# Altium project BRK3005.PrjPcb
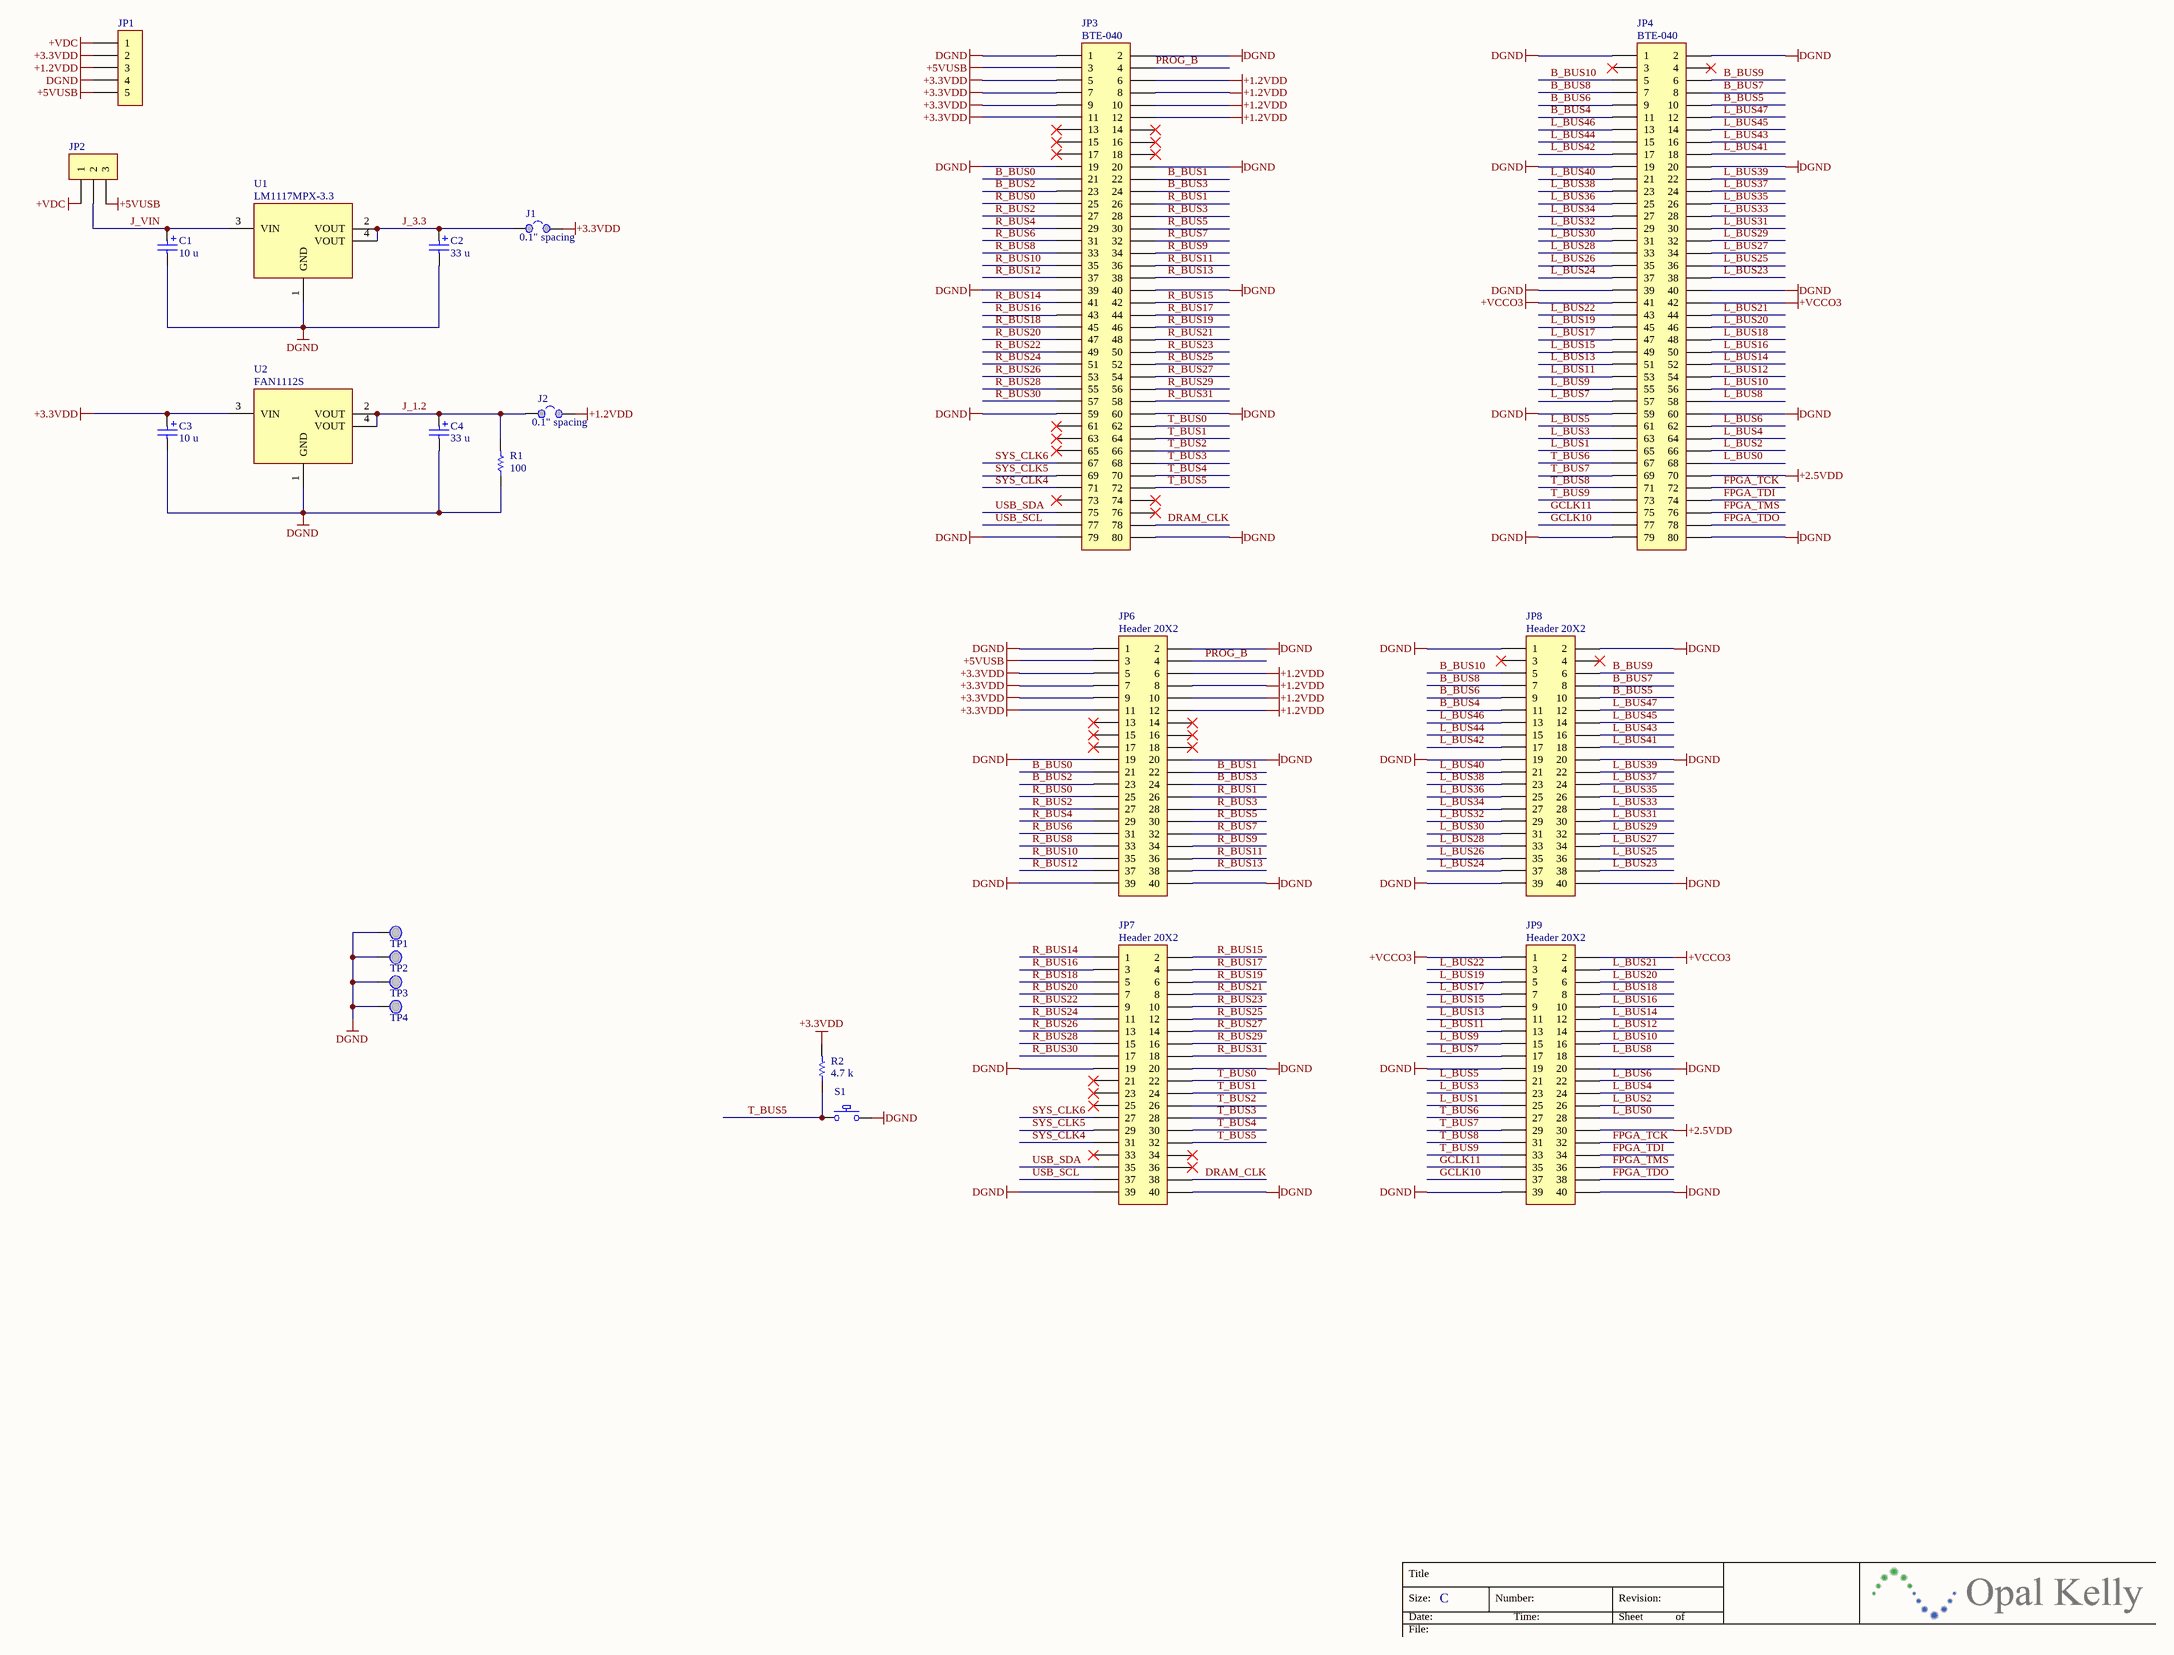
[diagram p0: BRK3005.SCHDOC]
1 sheet, 23 parts. Net scope: global (net labels, ports and power ports of the same name join across sheets).
Board file: BRK3005.PcbDoc

## Sheet BRK3005.SCHDOC: BRK3005
size C; Author: Garrick Kremesec; Organization: Opal Kelly; Address1: 13500 SW 72nd Ave, STE 120; Address2: Portland, OR  97223; Address3: http://www.opalkelly.com; DocumentNumber: xxx; Revision: 1; SheetNumber: 1; SheetTotal: 1; PageSetup: Record=PageOptions|CenterHorizontal=True|CenterVertical=True|PrintScale=0.54|XCorrection=1.00|YCorrection=1.00|PrintKind=0|BorderSize=5000000|LeftOffset=0|BottomOffset=0|Orientation=2|PaperLength=1000|PaperWidth=1000|Scale=100|PaperSource=7|PrintQuality=-4|MediaType=1|DitherType=10|PaperKind=Letter|PrintScaleMode=1

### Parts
C1  value 10 u  [TC3216-1206]  (hidden comment: SM-A, 10v, 10%)
C2  value 33 u  [TC3528-1411]  (hidden comment: SM-B, 10v, low-ESR)
C3  value 10 u  [TC3216-1206]  (hidden comment: SM-A, 10v, 10%)
C4  value 33 u  [TC3528-1411]  (hidden comment: SM-B, 10v, low-ESR)
J1  0.1" spacing  [HDR1X2]
J2  0.1" spacing  [HDR1X2]
JP1  Header, 6-Pin, Single Row  [HDR1X5]  (value not drawn)
JP2  *  [HDR1X3]  (value not drawn)
JP3  BTE-040  [BTE-040]
JP4  BTE-040  [BTE-040]
JP6  Header 20X2  [HDR2X20]
JP7  Header 20X2  [HDR2X20]
JP8  Header 20X2  [HDR2X20]
JP9  Header 20X2  [HDR2X20]
R1  value 100  [CR1608-0603]  (hidden comment: SM-0603, 5%, 1/10W)
R2  value 4.7 k  [CR1608-0603]  (hidden comment: SM-0603, 5%, 1/10W)
S1  SMD, tactile  [SW_BFS]  (value not drawn)
TP1  TESTPOINT  [TP_MED]  (value not drawn)
TP2  TESTPOINT  [TP_MED]  (value not drawn)
TP3  TESTPOINT  [TP_MED]  (value not drawn)
TP4  TESTPOINT  [TP_MED]  (value not drawn)
U1  ManufacturerPartNumber: LM1117MPX-3.3  [DSO-G3]  (hidden comment: 3.3v 800mA)
U2  ManufacturerPartNumber: FAN1112S  [DSO-G3]  (hidden comment: 1.2v 1A)

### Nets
+1.2VDD: J2.2 JP1.3 JP3.6 JP3.8 JP3.10 JP3.12 JP6.6 JP6.8 JP6.10 JP6.12
+2.5VDD: JP4.70 JP9.30
+3.3VDD: C3.1 J1.2 JP1.2 JP3.5 JP3.7 JP3.9 JP3.11 JP6.5 JP6.7 JP6.9 JP6.11 R2.2 U2.3(VIN)
+5VUSB: JP1.5 JP2.3 JP3.3 JP6.3
+VCCO3: JP4.41 JP4.42 JP9.1 JP9.2
+VDC: JP1.1 JP2.1
DGND: C1.2 C2.2 C3.2 C4.2 JP1.4 JP3.1 JP3.2 JP3.19 JP3.20 JP3.39 JP3.40 JP3.59 JP3.60 JP3.79 JP3.80 JP4.1 JP4.2 JP4.19 JP4.20 JP4.39 JP4.40 JP4.59 JP4.60 JP4.79 JP4.80 JP6.1 JP6.2 JP6.19 JP6.20 JP6.39 JP6.40 JP7.19 JP7.20 JP7.39 JP7.40 JP8.1 JP8.2 JP8.19 JP8.20 JP8.39 JP8.40 JP9.19 JP9.20 JP9.39 JP9.40 R1.1 S1.2 TP1.1(PIN) TP2.1(PIN) TP3.1(PIN) TP4.1(PIN) U1.1(GND) U2.1(GND)
B_BUS0: JP3.21 JP6.21
B_BUS1: JP3.22 JP6.22
B_BUS2: JP3.23 JP6.23
B_BUS3: JP3.24 JP6.24
B_BUS4: JP4.11 JP8.11
B_BUS5: JP4.10 JP8.10
B_BUS6: JP4.9 JP8.9
B_BUS7: JP4.8 JP8.8
B_BUS8: JP4.7 JP8.7
B_BUS9: JP4.6 JP8.6
B_BUS10: JP4.5 JP8.5
DRAM_CLK: JP3.78 JP7.38
FPGA_TCK: JP4.72 JP9.32
FPGA_TDI: JP4.74 JP9.34
FPGA_TDO: JP4.78 JP9.38
FPGA_TMS: JP4.76 JP9.36
GCLK10: JP4.77 JP9.37
GCLK11: JP4.75 JP9.35
J_1.2: C4.1 J2.1 R1.2 U2.2(VOUT) U2.4(VOUT)
J_3.3: C2.1 J1.1 U1.2(VOUT) U1.4(VOUT)
J_VIN: C1.1 JP2.2 U1.3(VIN)
L_BUS0: JP4.68 JP9.28
L_BUS1: JP4.65 JP9.25
L_BUS2: JP4.66 JP9.26
L_BUS3: JP4.63 JP9.23
L_BUS4: JP4.64 JP9.24
L_BUS5: JP4.61 JP9.21
L_BUS6: JP4.62 JP9.22
L_BUS7: JP4.57 JP9.17
L_BUS8: JP4.58 JP9.18
L_BUS9: JP4.55 JP9.15
L_BUS10: JP4.56 JP9.16
L_BUS11: JP4.53 JP9.13
L_BUS12: JP4.54 JP9.14
L_BUS13: JP4.51 JP9.11
L_BUS14: JP4.52 JP9.12
L_BUS15: JP4.49 JP9.9
L_BUS16: JP4.50 JP9.10
L_BUS17: JP4.47 JP9.7
L_BUS18: JP4.48 JP9.8
L_BUS19: JP4.45 JP9.5
L_BUS20: JP4.46 JP9.6
L_BUS21: JP4.44 JP9.4
L_BUS22: JP4.43 JP9.3
L_BUS23: JP4.38 JP8.38
L_BUS24: JP4.37 JP8.37
L_BUS25: JP4.36 JP8.36
L_BUS26: JP4.35 JP8.35
L_BUS27: JP4.34 JP8.34
L_BUS28: JP4.33 JP8.33
L_BUS29: JP4.32 JP8.32
L_BUS30: JP4.31 JP8.31
L_BUS31: JP4.30 JP8.30
L_BUS32: JP4.29 JP8.29
L_BUS33: JP4.28 JP8.28
L_BUS34: JP4.27 JP8.27
L_BUS35: JP4.26 JP8.26
L_BUS36: JP4.25 JP8.25
L_BUS37: JP4.24 JP8.24
L_BUS38: JP4.23 JP8.23
L_BUS39: JP4.22 JP8.22
L_BUS40: JP4.21 JP8.21
L_BUS41: JP4.18 JP8.18
L_BUS42: JP4.17 JP8.17
L_BUS43: JP4.16 JP8.16
L_BUS44: JP4.15 JP8.15
L_BUS45: JP4.14 JP8.14
L_BUS46: JP4.13 JP8.13
L_BUS47: JP4.12 JP8.12
PROG_B: JP3.4 JP6.4
R_BUS0: JP3.25 JP6.25
R_BUS1: JP3.26 JP6.26
R_BUS2: JP3.27 JP6.27
R_BUS3: JP3.28 JP6.28
R_BUS4: JP3.29 JP6.29
R_BUS5: JP3.30 JP6.30
R_BUS6: JP3.31 JP6.31
R_BUS7: JP3.32 JP6.32
R_BUS8: JP3.33 JP6.33
R_BUS9: JP3.34 JP6.34
R_BUS10: JP3.35 JP6.35
R_BUS11: JP3.36 JP6.36
R_BUS12: JP3.37 JP6.37
R_BUS13: JP3.38 JP6.38
R_BUS14: JP3.41 JP7.1
R_BUS15: JP3.42 JP7.2
R_BUS16: JP3.43 JP7.3
R_BUS17: JP3.44 JP7.4
R_BUS18: JP3.45 JP7.5
R_BUS19: JP3.46 JP7.6
R_BUS20: JP3.47 JP7.7
R_BUS21: JP3.48 JP7.8
R_BUS22: JP3.49 JP7.9
R_BUS23: JP3.50 JP7.10
R_BUS24: JP3.51 JP7.11
R_BUS25: JP3.52 JP7.12
R_BUS26: JP3.53 JP7.13
R_BUS27: JP3.54 JP7.14
R_BUS28: JP3.55 JP7.15
R_BUS29: JP3.56 JP7.16
R_BUS30: JP3.57 JP7.17
R_BUS31: JP3.58 JP7.18
SYS_CLK4: JP3.71 JP7.31
SYS_CLK5: JP3.69 JP7.29
SYS_CLK6: JP3.67 JP7.27
T_BUS0: JP3.62 JP7.22
T_BUS1: JP3.64 JP7.24
T_BUS2: JP3.66 JP7.26
T_BUS3: JP3.68 JP7.28
T_BUS4: JP3.70 JP7.30
T_BUS5: JP3.72 JP7.32 R2.1 S1.1
T_BUS6: JP4.67 JP9.27
T_BUS7: JP4.69 JP9.29
T_BUS8: JP4.71 JP9.31
T_BUS9: JP4.73 JP9.33
USB_SCL: JP3.77 JP7.37
USB_SDA: JP3.75 JP7.35

Not connected (* = marked no-connect by the designer): JP3 13* 14* 15* 16* 17* 18* 61* 63* 65* 73* 74* 76*; JP4 3* 4*; JP6 13* 14* 15* 16* 17* 18*; JP7 21* 23* 25* 33* 34* 36*; JP8 3* 4*

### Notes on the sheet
- Title
- Size:
- Date:
- File:
- C
- Number:
- Time:
- Revision:
- Sheet
- of

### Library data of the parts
C1 C3 = Capacitor Pol: Tantalum capacitor; Manufacturer: 13; PartNumber: 000018; ManufacturerPartNumber: T491A106K010AS; Class I: Passive
C2 C4 = Capacitor Pol: Tantalum capacitor; PartNumber: 000172; Class I: Passive
J1 J2 = Jumper 1X2: Header; PartNumber: 000173; Class I: Connector
JP1 = Header 1X5
JP2 = Header 1X3: Header, 3-Pin, Single Row
JP3 JP4 = BTE/BSE-040: Header/Socket - 80-pin - 0.80mm; Manufacturer: Samtech; PartNumber: 000059
JP6-JP9 = Header 20X2: Header, 20-Pin, Dual row; Manufacturer: Generic Components; Class I: Connector
R1 = Resistor: Thick-film resistor; Manufacturer: 25; PartNumber: 000110; ManufacturerPartNumber: 9C06031A4701JLHFT; Class I: Passive
R2 = Resistor: Thick-film resistor; Manufacturer: 25; PartNumber: 000127; ManufacturerPartNumber: 9C06031A4701JLHFT; Class I: Passive
S1 = SW-PB: Pushbutton; Manufacturer: 7; PartNumber: 000010; ManufacturerPartNumber: B3FS-1000P
U1 = LM1117: LDO regulator; Manufacturer: 4; PartNumber: 000156
U2 = FAN1112: LDO regulator; Manufacturer: 6; PartNumber: 000155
